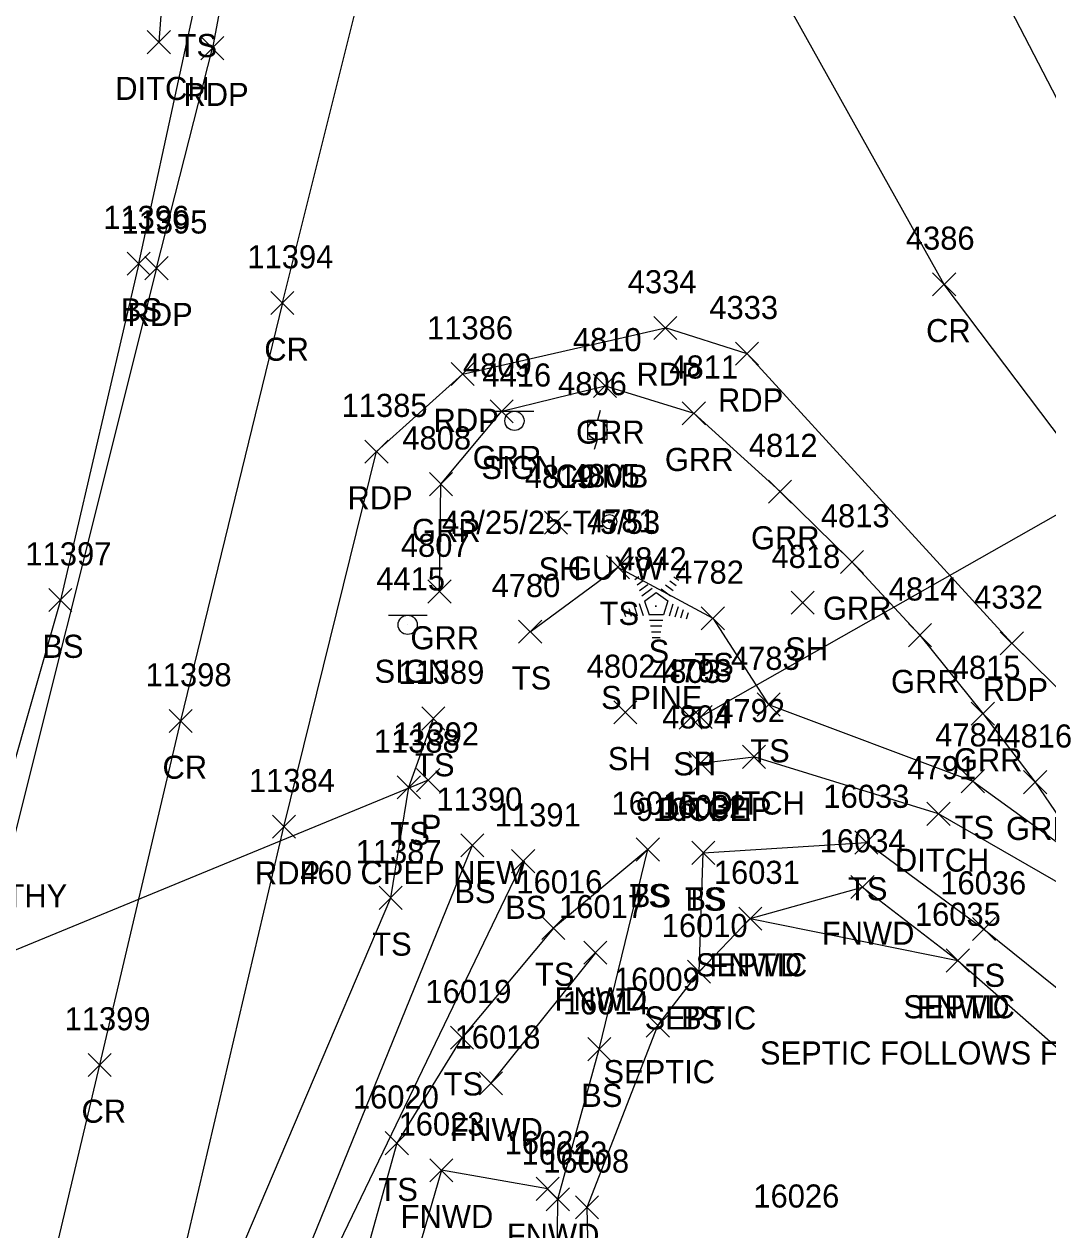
# Model space of a CAD drawing. Extents: x 1482574 to 1485769, y 580696 to 595649.
# Drawn here: x 1483500.5 to 1483589.1, y 583487.9 to 583592.2 of the extents above; entities that cross this region are included whole.
import ezdxf

# ---------------------------------------------------------------- set-up
doc = ezdxf.new("R2010")
doc.units = 0
for name, color, linetype in [('D_A', 7, 'Continuous'), ('D_C', 7, 'Continuous'), ('D_I', 7, 'Continuous'), ('D_TIC', 7, 'Continuous'), ('DCP', 7, 'Continuous'), ('DD', 7, 'Continuous'), ('L_A', 7, 'Continuous'), ('L_C', 7, 'Continuous'), ('L_I', 7, 'Continuous'), ('L_TIC', 7, 'Continuous'), ('LELB', 7, 'Continuous'), ('LFNC', 7, 'Continuous'), ('LTC', 7, 'Continuous'), ('M_C', 7, 'Continuous'), ('P_A', 7, 'Continuous'), ('P_I', 7, 'Continuous'), ('P_TIC', 7, 'Continuous'), ('PET', 7, 'Continuous'), ('PRC', 7, 'Continuous'), ('R_A', 7, 'Continuous'), ('R_I', 7, 'Continuous'), ('R_TIC', 7, 'Continuous'), ('RGR', 7, 'Continuous'), ('S_A', 7, 'Continuous'), ('S_I', 7, 'Continuous'), ('SSGN', 7, 'Continuous'), ('U_A', 7, 'Continuous'), ('U_C', 7, 'Continuous'), ('U_I', 7, 'Continuous'), ('U_TIC', 7, 'Continuous'), ('UP', 7, 'Continuous'), ('UPGW', 7, 'Continuous'), ('USA', 7, 'Continuous')]:
    doc.layers.add(name, color=color, linetype=linetype)

msp = doc.modelspace()

# ---------------------------------------------------------------- linework, layer by layer
at = {"layer": 'D_TIC'}
for points in [[(1483511.12, 583589.65), (1483513.12, 583591.65)], [(1483513.12, 583589.65), (1483511.12, 583591.65)], [(1483558.02, 583531.26), (1483560.02, 583533.26)], [(1483560.02, 583531.26), (1483558.02, 583533.26)], [(1483562.63, 583527.81), (1483564.63, 583529.81)], [(1483564.63, 583527.81), (1483562.63, 583529.81)], [(1483558.02, 583527.26), (1483560.02, 583529.26)], [(1483560.02, 583527.26), (1483558.02, 583529.26)], [(1483534.43, 583525.79), (1483536.43, 583527.79)], [(1483536.43, 583525.79), (1483534.43, 583527.79)], [(1483578.6, 583522.87), (1483580.6, 583524.87)], [(1483580.6, 583522.87), (1483578.6, 583524.87)]]:
    msp.add_lwpolyline(points, dxfattribs=at)
at = {"layer": 'DCP'}
for points in [[(1483620.43, 583567.1), (1483559.02, 583532.26)], [(1483535.43, 583526.79), (1483491.9, 583508.86)]]:
    msp.add_lwpolyline(points, dxfattribs=at)
at = {"layer": 'DD'}
for points in [[(1483512.61, 583622.6), (1483514.79, 583619.61), (1483513.51, 583609.21), (1483512.11, 583590.65)], [(1483559.02, 583528.26), (1483563.63, 583528.81)], [(1483625.06, 583490.59), (1483611.42, 583502.51), (1483594.01, 583515.58), (1483579.6, 583523.87), (1483563.63, 583528.81)]]:
    msp.add_lwpolyline(points, dxfattribs=at)
at = {"layer": 'L_TIC'}
for points in [[(1483509.38, 583570.49), (1483511.38, 583572.49)], [(1483511.38, 583570.49), (1483509.38, 583572.49)], [(1483545.5, 583548.07), (1483547.5, 583550.07)], [(1483547.5, 583548.07), (1483545.5, 583550.07)], [(1483550.86, 583544.22), (1483552.86, 583546.22)], [(1483552.86, 583544.22), (1483550.86, 583546.22)], [(1483502.6, 583541.37), (1483504.6, 583543.37)], [(1483504.6, 583541.37), (1483502.6, 583543.37)], [(1483566.84, 583541.15), (1483568.84, 583543.15)], [(1483568.84, 583541.15), (1483566.84, 583543.15)], [(1483559.07, 583539.8), (1483561.07, 583541.79)], [(1483561.07, 583539.8), (1483559.07, 583541.79)], [(1483543.26, 583538.63), (1483545.26, 583540.63)], [(1483545.26, 583538.63), (1483543.26, 583540.63)], [(1483563.9, 583532.33), (1483565.9, 583534.33)], [(1483565.9, 583532.33), (1483563.9, 583534.33)], [(1483534.89, 583531.12), (1483536.89, 583533.12)], [(1483536.89, 583531.12), (1483534.89, 583533.12)], [(1483551.5, 583531.65), (1483553.5, 583533.64)], [(1483553.5, 583531.65), (1483551.5, 583533.64)], [(1483557.16, 583531.2), (1483559.16, 583533.2)], [(1483559.16, 583531.2), (1483557.16, 583533.2)], [(1483581.58, 583525.7), (1483583.58, 583527.7)], [(1483583.58, 583525.7), (1483581.58, 583527.7)], [(1483532.76, 583525.17), (1483534.76, 583527.17)], [(1483534.76, 583525.17), (1483532.76, 583527.17)], [(1483572.36, 583520.39), (1483574.36, 583522.39)], [(1483574.36, 583520.39), (1483572.36, 583522.39)], [(1483538.26, 583520.15), (1483540.26, 583522.15)], [(1483540.26, 583520.15), (1483538.26, 583522.15)], [(1483553.45, 583519.79), (1483555.45, 583521.79)], [(1483555.45, 583519.79), (1483553.45, 583521.79)], [(1483553.45, 583519.79), (1483555.45, 583521.79)], [(1483555.45, 583519.79), (1483553.45, 583521.79)], [(1483558.24, 583519.5), (1483560.24, 583521.5)], [(1483560.24, 583519.5), (1483558.24, 583521.5)], [(1483558.24, 583519.5), (1483560.24, 583521.5)], [(1483560.24, 583519.5), (1483558.24, 583521.5)], [(1483542.66, 583518.78), (1483544.66, 583520.78)], [(1483544.66, 583518.78), (1483542.66, 583520.78)], [(1483572.03, 583516.54), (1483574.03, 583518.54)], [(1483574.03, 583516.54), (1483572.03, 583518.54)], [(1483531.19, 583515.6), (1483533.19, 583517.6)], [(1483533.19, 583515.6), (1483531.19, 583517.6)], [(1483545.27, 583512.99), (1483547.27, 583514.99)], [(1483547.27, 583512.99), (1483545.27, 583514.99)], [(1483562.31, 583513.81), (1483564.31, 583515.81)], [(1483564.31, 583513.81), (1483562.31, 583515.81)], [(1483582.54, 583512.9), (1483584.54, 583514.9)], [(1483584.54, 583512.9), (1483582.54, 583514.9)], [(1483548.91, 583510.85), (1483550.91, 583512.85)], [(1483550.91, 583510.85), (1483548.91, 583512.85)], [(1483580.28, 583510.18), (1483582.28, 583512.18)], [(1483582.28, 583510.18), (1483580.28, 583512.18)], [(1483557.88, 583509.21), (1483559.88, 583511.21)], [(1483559.88, 583509.21), (1483557.88, 583511.21)], [(1483537.36, 583503.5), (1483539.36, 583505.5)], [(1483539.36, 583503.5), (1483537.36, 583505.5)], [(1483549.24, 583502.51), (1483551.24, 583504.51)], [(1483551.24, 583502.51), (1483549.24, 583504.51)], [(1483539.87, 583499.56), (1483541.87, 583501.56)], [(1483541.87, 583499.56), (1483539.87, 583501.56)], [(1483531.72, 583494.37), (1483533.72, 583496.37)], [(1483533.72, 583494.37), (1483531.72, 583496.37)], [(1483535.58, 583492.03), (1483537.58, 583494.03)], [(1483537.58, 583492.03), (1483535.58, 583494.03)], [(1483544.77, 583490.42), (1483546.77, 583492.42)], [(1483546.77, 583490.42), (1483544.77, 583492.42)], [(1483545.66, 583489.52), (1483547.66, 583491.52)], [(1483547.66, 583489.52), (1483545.66, 583491.52)]]:
    msp.add_lwpolyline(points, dxfattribs=at)
at = {"layer": 'LELB'}
for points in [[(1483510.38, 583571.49), (1483515.34, 583594.36)], [(1483510.38, 583571.49), (1483503.6, 583542.37), (1483494.4, 583510.2)], [(1483544.26, 583539.63), (1483551.86, 583545.22), (1483560.07, 583540.8), (1483564.9, 583533.33), (1483582.58, 583526.7), (1483592.71, 583519.37), (1483604.99, 583512.56), (1483626.49, 583492.24)], [(1483503.49, 583426.56), (1483504.76, 583434.71), (1483516.69, 583480.14), (1483532.19, 583516.6), (1483533.76, 583526.17), (1483535.89, 583532.12)], [(1483510.71, 583429.98), (1483509.06, 583432.18), (1483521.61, 583477.68), (1483539.26, 583521.15)], [(1483559.24, 583520.5), (1483573.36, 583521.39), (1483583.54, 583513.9), (1483603.61, 583497.75), (1483618.64, 583480.38)], [(1483554.45, 583520.79), (1483546.27, 583513.99), (1483538.36, 583504.5), (1483532.72, 583495.37), (1483525.63, 583469.86)], [(1483585.25, 583448.14), (1483566.81, 583447.24), (1483552.92, 583458.86), (1483546.47, 583472.86), (1483546.66, 583490.52), (1483550.24, 583503.51), (1483554.45, 583520.79)], [(1483558.88, 583510.21), (1483559.24, 583520.5)], [(1483510.71, 583429.98), (1483512.13, 583432.27), (1483523.58, 583478.1), (1483543.66, 583519.78)]]:
    msp.add_lwpolyline(points, dxfattribs=at)
at = {"layer": 'LFNC'}
for points in [[(1483563.31, 583514.81), (1483573.03, 583517.54), (1483581.28, 583511.18), (1483599.84, 583494.9), (1483609.97, 583484.97), (1483617.31, 583477.83)], [(1483549.91, 583511.85), (1483540.87, 583500.56)], [(1483545.77, 583491.42), (1483536.58, 583493.03), (1483530.17, 583470.95)]]:
    msp.add_lwpolyline(points, dxfattribs=at)
at = {"layer": 'LTC'}
for p, q in [((1483553.32, 583544.15), (1483553.67, 583544.4)), ((1483556.71, 583544.39), (1483557.13, 583544.08)), ((1483553.52, 583543.68), (1483554.05, 583544.06)), ((1483553.73, 583543.21), (1483554.44, 583543.73)), ((1483553.94, 583542.75), (1483554.82, 583543.39)), ((1483555.6, 583543.34), (1483556.41, 583542.75)), ((1483555.97, 583543.69), (1483556.65, 583543.2)), ((1483556.34, 583544.04), (1483556.89, 583543.64)), ((1483553.71, 583542.07), (1483554.04, 583541.05)), ((1483554.17, 583542.29), (1483555.18, 583543.03)), ((1483554.17, 583542.29), (1483554.56, 583541.1)), ((1483555.18, 583543.03), (1483556.18, 583542.3)), ((1483556.18, 583542.3), (1483555.79, 583541.1)), ((1483556.61, 583542.03), (1483556.28, 583540.99)), ((1483552.35, 583541.42), (1483552.5, 583540.96)), ((1483552.8, 583541.64), (1483553.01, 583540.99)), ((1483553.26, 583541.86), (1483553.53, 583541.02)), ((1483555.79, 583541.1), (1483554.56, 583541.1)), ((1483557.06, 583541.78), (1483556.77, 583540.9)), ((1483557.5, 583541.53), (1483557.27, 583540.8)), ((1483557.95, 583541.28), (1483557.76, 583540.71)), ((1483555.75, 583540.6), (1483554.6, 583540.6)), ((1483555.66, 583540.1), (1483554.68, 583540.1)), ((1483555.58, 583539.6), (1483554.75, 583539.6)), ((1483555.5, 583539.1), (1483554.82, 583539.1))]:
    msp.add_line(p, q, dxfattribs=at)
at = {"layer": 'P_TIC'}
for points in [[(1483515.76, 583589.13), (1483517.76, 583591.13)], [(1483517.76, 583589.13), (1483515.76, 583591.13)], [(1483510.92, 583570.09), (1483512.92, 583572.09)], [(1483512.92, 583570.09), (1483510.92, 583572.09)], [(1483579.09, 583568.69), (1483581.09, 583570.69)], [(1483581.09, 583568.69), (1483579.09, 583570.69)], [(1483521.82, 583567.08), (1483523.82, 583569.08)], [(1483523.82, 583567.08), (1483521.82, 583569.08)], [(1483554.97, 583564.92), (1483556.97, 583566.92)], [(1483556.97, 583564.92), (1483554.97, 583566.92)], [(1483562.03, 583562.7), (1483564.03, 583564.69)], [(1483564.03, 583562.7), (1483562.03, 583564.69)], [(1483537.41, 583560.93), (1483539.41, 583562.93)], [(1483539.41, 583560.93), (1483537.41, 583562.93)], [(1483529.96, 583554.22), (1483531.96, 583556.22)], [(1483531.96, 583554.22), (1483529.96, 583556.22)], [(1483584.95, 583537.63), (1483586.95, 583539.63)], [(1483586.95, 583537.63), (1483584.95, 583539.63)], [(1483513.01, 583530.91), (1483515.01, 583532.91)], [(1483515.01, 583530.91), (1483513.01, 583532.91)], [(1483521.95, 583521.76), (1483523.95, 583523.76)], [(1483523.95, 583521.76), (1483521.95, 583523.76)], [(1483506, 583501.14), (1483508, 583503.14)], [(1483508, 583501.14), (1483506, 583503.14)]]:
    msp.add_lwpolyline(points, dxfattribs=at)
at = {"layer": 'PET'}
for points in [[(1483628.83, 583528.85), (1483617.42, 583543.37), (1483595.05, 583575.78), (1483578.7, 583607.28), (1483568.42, 583641.78), (1483564.67, 583676.42), (1483566.47, 583711.48), (1483571.17, 583746.23), (1483573.69, 583780.53), (1483577.92, 583804.21)], [(1483359.39, 583657.75), (1483395.14, 583652.04), (1483432.05, 583647.87), (1483468.1, 583644.53), (1483508.57, 583640.7), (1483520.18, 583632.15), (1483523.61, 583626.74), (1483516.76, 583590.13)], [(1483511.92, 583571.09), (1483516.76, 583590.13)], [(1483511.92, 583571.09), (1483496.28, 583508.73), (1483487.22, 583470.03), (1483474.79, 583419.59), (1483466.19, 583381.57), (1483457.71, 583345.65), (1483450.2, 583313.7), (1483440.82, 583274.3), (1483435.83, 583252.18), (1483423.1, 583202.8), (1483409.25, 583154.54), (1483397.16, 583119.52), (1483379.57, 583084.11), (1483352.88, 583049.38), (1483319.73, 583018.16), (1483283.7, 582994.02), (1483248.61, 582977.24), (1483209.52, 582964.18), (1483165.99, 582956.07), (1483134.36, 582954.23), (1483102.75, 582955.66), (1483067.48, 582958.18), (1483032.8, 582960.58), (1482992.37, 582962.35)], [(1483538.41, 583561.93), (1483555.97, 583565.92)], [(1483734.47, 583384.83), (1483710.77, 583410.08), (1483685.69, 583436.09), (1483659.83, 583462.34), (1483636.38, 583486.71), (1483612.84, 583512.18), (1483585.95, 583538.63), (1483563.03, 583563.69), (1483555.97, 583565.92)], [(1483273.74, 582962.79), (1483311.58, 582984.53), (1483347.52, 583011.78), (1483361.65, 583025.61), (1483391.28, 583060.08), (1483405.01, 583082.59), (1483417.18, 583108.38), (1483428.84, 583140.42), (1483442.12, 583183.96), (1483456.03, 583237.8), (1483469.06, 583293.98), (1483481.7, 583346.34), (1483492.55, 583392.93), (1483501.55, 583432.11), (1483512.98, 583480.3), (1483522.95, 583522.76), (1483530.96, 583555.22), (1483538.41, 583561.93)]]:
    msp.add_lwpolyline(points, dxfattribs=at)
at = {"layer": 'PRC'}
for points in [[(1483618.73, 583521.67), (1483605.12, 583536.57), (1483580.09, 583569.69), (1483562.2, 583601.73), (1483551.28, 583637.89), (1483548.66, 583672.74), (1483550.4, 583708.14), (1483555.34, 583744.78), (1483561.11, 583779.91), (1483565.84, 583808.31), (1483572.09, 583842.87), (1483580.82, 583892.49), (1483589.4, 583942.82)], [(1483522.82, 583568.08), (1483530.39, 583598.35)], [(1483522.82, 583568.08), (1483514.01, 583531.91), (1483507, 583502.14), (1483494.18, 583448.16), (1483483.86, 583404.31), (1483476.15, 583371.83), (1483469.12, 583341.9), (1483461.79, 583311.09), (1483452.64, 583272.5), (1483447.07, 583249.26), (1483434.31, 583199.7), (1483420.43, 583150.9), (1483407.88, 583114.59), (1483388.93, 583076.96), (1483361.17, 583040.76), (1483327.65, 583009.41), (1483290.99, 582984.57)]]:
    msp.add_lwpolyline(points, dxfattribs=at)
at = {"layer": 'R_TIC'}
for points in [[(1483549.74, 583559.91), (1483551.74, 583561.91)], [(1483551.74, 583559.91), (1483549.74, 583561.91)], [(1483540.8, 583557.71), (1483542.8, 583559.71)], [(1483542.8, 583557.71), (1483540.8, 583559.71)], [(1483557.43, 583557.54), (1483559.43, 583559.54)], [(1483559.43, 583557.54), (1483557.43, 583559.54)], [(1483535.54, 583551.4), (1483537.54, 583553.4)], [(1483537.54, 583551.4), (1483535.54, 583553.4)], [(1483564.89, 583550.76), (1483566.88, 583552.76)], [(1483566.88, 583550.76), (1483564.89, 583552.76)], [(1483571.11, 583544.67), (1483573.11, 583546.67)], [(1483573.11, 583544.67), (1483571.11, 583546.67)], [(1483535.41, 583542.11), (1483537.41, 583544.11)], [(1483537.41, 583542.11), (1483535.41, 583544.11)], [(1483577, 583538.33), (1483579, 583540.33)], [(1483579, 583538.33), (1483577, 583540.33)], [(1483582.44, 583531.55), (1483584.44, 583533.55)], [(1483584.44, 583531.55), (1483582.44, 583533.55)], [(1483586.97, 583525.61), (1483588.97, 583527.61)], [(1483588.97, 583525.61), (1483586.97, 583527.61)]]:
    msp.add_lwpolyline(points, dxfattribs=at)
at = {"layer": 'RGR'}
msp.add_lwpolyline([(1483536.41, 583543.11), (1483536.54, 583552.4), (1483541.8, 583558.71), (1483550.74, 583560.91), (1483558.43, 583558.54), (1483565.89, 583551.76), (1483572.11, 583545.67), (1483578, 583539.33), (1483583.44, 583532.55), (1483587.97, 583526.61), (1483591.81, 583521)], dxfattribs=at)
at = {"layer": 'SSGN'}
for p, q in [((1483541.26, 583558.71), (1483544.59, 583558.71)), ((1483542.9, 583557.88), (1483542.9, 583557.88)), ((1483532.01, 583541.07), (1483535.34, 583541.07)), ((1483533.66, 583540.23), (1483533.66, 583540.23))]:
    msp.add_line(p, q, dxfattribs=at)
for centre in [(1483542.9, 583557.88), (1483533.66, 583540.23)]:
    msp.add_circle(centre, 0.833, dxfattribs=at)
at = {"layer": 'U_TIC'}
for points in [[(1483562.31, 583513.81), (1483564.31, 583515.81)], [(1483564.31, 583513.81), (1483562.31, 583515.81)], [(1483580.28, 583510.18), (1483582.28, 583512.18)], [(1483582.28, 583510.18), (1483580.28, 583512.18)], [(1483557.88, 583509.21), (1483559.88, 583511.21)], [(1483559.88, 583509.21), (1483557.88, 583511.21)], [(1483554.31, 583504.56), (1483556.31, 583506.56)], [(1483556.31, 583504.56), (1483554.31, 583506.56)], [(1483548.19, 583488.82), (1483550.19, 583490.82)], [(1483550.19, 583488.82), (1483548.19, 583490.82)]]:
    msp.add_lwpolyline(points, dxfattribs=at)
at = {"layer": 'UP'}
for p, q in [((1483550.33, 583558.77), (1483550.08, 583557.94)), ((1483549.24, 583556.27), (1483549.24, 583557.94)), ((1483549.24, 583557.94), (1483550.91, 583557.94)), ((1483550.91, 583557.94), (1483550.91, 583556.27)), ((1483550.08, 583557.1), (1483550.08, 583557.1)), ((1483550.91, 583556.27), (1483549.24, 583556.27)), ((1483549.83, 583555.44), (1483550.08, 583556.27))]:
    msp.add_line(p, q, dxfattribs=at)
msp.add_circle((1483550.08, 583557.1), 0.833, dxfattribs=at)
at = {"layer": 'UPGW'}
for radius in [0.625, 0.0833]:
    msp.add_circle((1483551.13, 583549.15), radius, dxfattribs=at)
at = {"layer": 'USA'}
msp.add_lwpolyline([(1483586.4, 583459.08), (1483572.49, 583459.41), (1483556.32, 583464.08), (1483549.53, 583473.89), (1483549.19, 583489.82), (1483555.31, 583505.56), (1483558.88, 583510.21), (1483563.31, 583514.81), (1483581.28, 583511.18)], dxfattribs=at)

# ---------------------------------------------------------------- texts
at = {"layer": 'D_A'}
for s, p in [('DITCH', (1483508.35, 583585.65)), ('P', (1483558.4, 583527.26)), ('DITCH', (1483559.87, 583523.81)), ('DITCH', (1483555.26, 583523.26)), ('P', (1483534.8, 583521.79)), ('DITCH', (1483575.83, 583518.87))]:
    msp.add_text(s, height=2, dxfattribs=at).set_placement(p)
at = {"layer": 'D_C'}
for s, p in [('910CPEP', (1483553.41, 583523.26)), ('460 CPEP NEW', (1483524.37, 583517.79))]:
    msp.add_text(s, height=2, dxfattribs=at).set_placement(p)
at = {"layer": 'D_I'}
for s, p in [('4793', (1483555.76, 583535.26)), ('4792', (1483560.37, 583531.81)), ('4804', (1483555.69, 583531.26)), ('11392', (1483532.4, 583529.79)), ('4791', (1483576.91, 583526.87))]:
    msp.add_text(s, height=2, dxfattribs=at).set_placement(p)
at = {"layer": 'L_A'}
for s, p in [('TS', (1483513.75, 583589.36)), ('BS', (1483508.83, 583566.49)), ('SH', (1483544.99, 583544.07)), ('TS', (1483550.27, 583540.22)), ('BS', (1483502.04, 583537.37)), ('S', (1483554.51, 583536.94)), ('SH', (1483566.33, 583537.15)), ('TS', (1483558.48, 583535.8)), ('TS', (1483542.67, 583534.63)), ('SH', (1483550.98, 583527.65)), ('TS', (1483563.31, 583528.33)), ('TS', (1483534.3, 583527.12)), ('SH', (1483556.65, 583527.2)), ('TS', (1483580.99, 583521.7)), ('TS', (1483532.17, 583521.17)), ('BS', (1483537.7, 583516.15)), ('TS', (1483571.77, 583516.39)), ('TS', (1483552.86, 583515.79)), ('BS', (1483552.89, 583515.79)), ('TS', (1483557.65, 583515.5)), ('BS', (1483557.69, 583515.5)), ('BS', (1483542.1, 583514.78)), ('FNWD', (1483569.5, 583512.54)), ('TS', (1483530.59, 583511.6)), ('FNWD', (1483559.77, 583509.81)), ('TS', (1483544.68, 583508.99)), ('TS', (1483581.95, 583508.9)), ('FNWD', (1483546.37, 583506.85)), ('FNWD', (1483577.74, 583506.18)), ('BS', (1483557.32, 583505.21)), ('TS', (1483536.77, 583499.5)), ('BS', (1483548.68, 583498.51)), ('FNWD', (1483537.34, 583495.56)), ('TS', (1483531.13, 583490.37)), ('FNWD', (1483533.05, 583488.03)), ('FNWD', (1483542.24, 583486.42))]:
    msp.add_text(s, height=2, dxfattribs=at).set_placement(p)
at = {"layer": 'L_C'}
for s, p in [('S PINE', (1483550.4, 583532.94)), ('SEPTIC FOLLOWS FNWD', (1483564.15, 583502.18))]:
    msp.add_text(s, height=2, dxfattribs=at).set_placement(p)
at = {"layer": 'L_I'}
for s, p in [('11396', (1483507.31, 583574.49)), ('4819', (1483543.8, 583552.07)), ('4781', (1483549.17, 583548.22)), ('11397', (1483500.58, 583545.37)), ('4842', (1483551.86, 583544.94)), ('4818', (1483565.15, 583545.15)), ('4782', (1483556.81, 583543.79)), ('4780', (1483540.92, 583542.63)), ('4783', (1483561.64, 583536.33)), ('11389', (1483532.86, 583535.12)), ('4802', (1483549.16, 583535.65)), ('4803', (1483554.82, 583535.2)), ('4784', (1483579.32, 583529.7)), ('11388', (1483530.73, 583529.17)), ('16033', (1483569.64, 583524.39)), ('11390', (1483536.15, 583524.15)), ('16015', (1483551.3, 583523.79)), ('16015', (1483551.3, 583523.79)), ('16032', (1483555.53, 583523.5)), ('16032', (1483555.53, 583523.5)), ('11391', (1483541.2, 583522.78)), ('16034', (1483569.32, 583520.54)), ('11387', (1483529.16, 583519.6)), ('16031', (1483560.16, 583517.81)), ('16016', (1483543.07, 583516.99)), ('16036', (1483579.76, 583516.9)), ('16017', (1483546.76, 583514.85)), ('16035', (1483577.56, 583514.18)), ('16010', (1483555.65, 583513.21)), ('16019', (1483535.2, 583507.5)), ('16014', (1483547.09, 583506.51)), ('16018', (1483537.72, 583503.56)), ('16020', (1483528.92, 583498.37)), ('16023', (1483532.87, 583496.03)), ('16022', (1483542.05, 583494.42)), ('16013', (1483543.51, 583493.52)), ('16026', (1483563.58, 583489.8))]:
    msp.add_text(s, height=2, dxfattribs=at).set_placement(p)
at = {"layer": 'LTC'}
msp.add_text('.', height=1.04, rotation=270, dxfattribs=at).set_placement((1483555.06, 583542.04))
at = {"layer": 'M_C'}
msp.add_text('IRON PIN WITH CAP :TIMOTHY', height=2, dxfattribs=at).set_placement((1483464.97, 583515.78))
at = {"layer": 'P_A'}
for s, p in [('RDP', (1483514.25, 583585.13)), ('RDP', (1483509.41, 583566.09)), ('CR', (1483578.53, 583564.69)), ('CR', (1483521.25, 583563.08)), ('RDP', (1483553.46, 583560.92)), ('RDP', (1483560.52, 583558.69)), ('RDP', (1483535.9, 583556.93)), ('RDP', (1483528.45, 583550.22)), ('RDP', (1483583.44, 583533.63)), ('CR', (1483512.44, 583526.91)), ('RDP', (1483520.44, 583517.76)), ('CR', (1483505.43, 583497.14))]:
    msp.add_text(s, height=2, dxfattribs=at).set_placement(p)
at = {"layer": 'P_I'}
for s, p in [('11395', (1483508.89, 583574.09)), ('4386', (1483576.78, 583572.69)), ('11394', (1483519.79, 583571.08)), ('4334', (1483552.71, 583568.92)), ('4333', (1483559.77, 583566.69)), ('11386', (1483535.34, 583564.93)), ('11385', (1483527.94, 583558.22)), ('4332', (1483582.69, 583541.63)), ('11398', (1483510.98, 583534.91)), ('11384', (1483519.92, 583525.76)), ('11399', (1483503.97, 583505.14))]:
    msp.add_text(s, height=2, dxfattribs=at).set_placement(p)
at = {"layer": 'R_A'}
for p in [(1483548.23, 583555.91), (1483539.29, 583553.71), (1483555.92, 583553.54), (1483534.03, 583547.4), (1483563.37, 583546.76), (1483569.6, 583540.67), (1483533.9, 583538.11), (1483575.49, 583534.33), (1483580.93, 583527.55), (1483585.45, 583521.61)]:
    msp.add_text('GRR', height=2, dxfattribs=at).set_placement(p)
at = {"layer": 'R_I'}
for s, p in [('4810', (1483547.96, 583563.91)), ('4809', (1483538.45, 583561.71)), ('4811', (1483556.31, 583561.54)), ('4808', (1483533.2, 583555.4)), ('4812', (1483563.19, 583554.76)), ('4813', (1483569.42, 583548.67)), ('4807', (1483533.07, 583546.11)), ('4814', (1483575.3, 583542.33)), ('4815', (1483580.75, 583535.55)), ('4816', (1483585.22, 583529.61))]:
    msp.add_text(s, height=2, dxfattribs=at).set_placement(p)
at = {"layer": 'S_A'}
for p in [(1483540.04, 583552.85), (1483530.79, 583535.21)]:
    msp.add_text('SIGN', height=2, dxfattribs=at).set_placement(p)
at = {"layer": 'S_I'}
for s, p in [('4416', (1483540.13, 583560.85)), ('4415', (1483530.94, 583543.21))]:
    msp.add_text(s, height=2, dxfattribs=at).set_placement(p)
at = {"layer": 'U_A'}
for s, p in [('COMB', (1483546.46, 583552.1)), ('GUYW', (1483547.52, 583544.14)), ('SEPTIC', (1483558.59, 583509.81)), ('SEPTIC', (1483576.56, 583506.18)), ('SEPTIC', (1483554.17, 583505.21)), ('SEPTIC', (1483550.6, 583500.56))]:
    msp.add_text(s, height=2, dxfattribs=at).set_placement(p)
at = {"layer": 'U_C'}
msp.add_text('43/25/25-T/5/53', height=2, dxfattribs=at).set_placement((1483536.63, 583548.1))
at = {"layer": 'U_I'}
for s, p in [('4806', (1483546.68, 583560.1)), ('4805', (1483547.79, 583552.15)), ('16031', (1483560.16, 583517.81)), ('16035', (1483577.56, 583514.18)), ('16010', (1483555.65, 583513.21)), ('16009', (1483551.51, 583508.56)), ('16008', (1483545.39, 583492.82))]:
    msp.add_text(s, height=2, dxfattribs=at).set_placement(p)

doc.saveas('drawing.dxf')
